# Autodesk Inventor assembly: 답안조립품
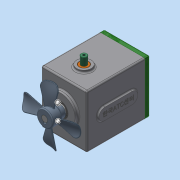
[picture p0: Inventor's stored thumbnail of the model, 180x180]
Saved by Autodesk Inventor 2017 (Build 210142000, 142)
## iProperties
Part Number: 답안조립품
Material: 일반
Document SubType Name: Assembly
Designer: MRC
Author: MRC
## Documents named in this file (17)
- C:\Users\MRC\Desktop\610205V1004\답안조립품.iam
- C:\Users\MRC\Desktop\610205V1004\멈춤나사 M3x8.ipt
- C:\Users\MRC\Desktop\610205V1004\메인 기어 축.ipt
- C:\Users\MRC\Desktop\610205V1004\베어링 608.ipt
- C:\Users\MRC\Desktop\610205V1004\베어링 6903.ipt
- C:\Users\MRC\Desktop\610205V1004\본체.ipt
- C:\Users\MRC\Desktop\610205V1004\볼트 M4 x 10.ipt
- C:\Users\MRC\Desktop\610205V1004\부시.ipt
- C:\Users\MRC\Desktop\610205V1004\서브 기어 축.ipt
- C:\Users\MRC\Desktop\610205V1004\슬라이더.ipt
- C:\Users\MRC\Desktop\610205V1004\오일 실 8 22 7.ipt
- C:\Users\MRC\Desktop\610205V1004\오일 실 17 30 8.ipt
- C:\Users\MRC\Desktop\610205V1004\커버.ipt
- C:\Users\MRC\Desktop\610205V1004\키 5 x 5 x 24.ipt
- C:\Users\MRC\Desktop\610205V1004\팬날개.ipt
- 팬날개.ipt
- C:\Users\MRC\Desktop\610205V1004\가변스프링.ipt
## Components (1 placed, 1 different names)
1. 가변스프링:1
